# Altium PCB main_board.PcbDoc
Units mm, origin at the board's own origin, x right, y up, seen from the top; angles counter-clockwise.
Board outline 32.69 x 33.15 mm, 2 copper layers (Top Layer, Bottom Layer); 5 components, 23 nets, 61 pads, 28 vias.
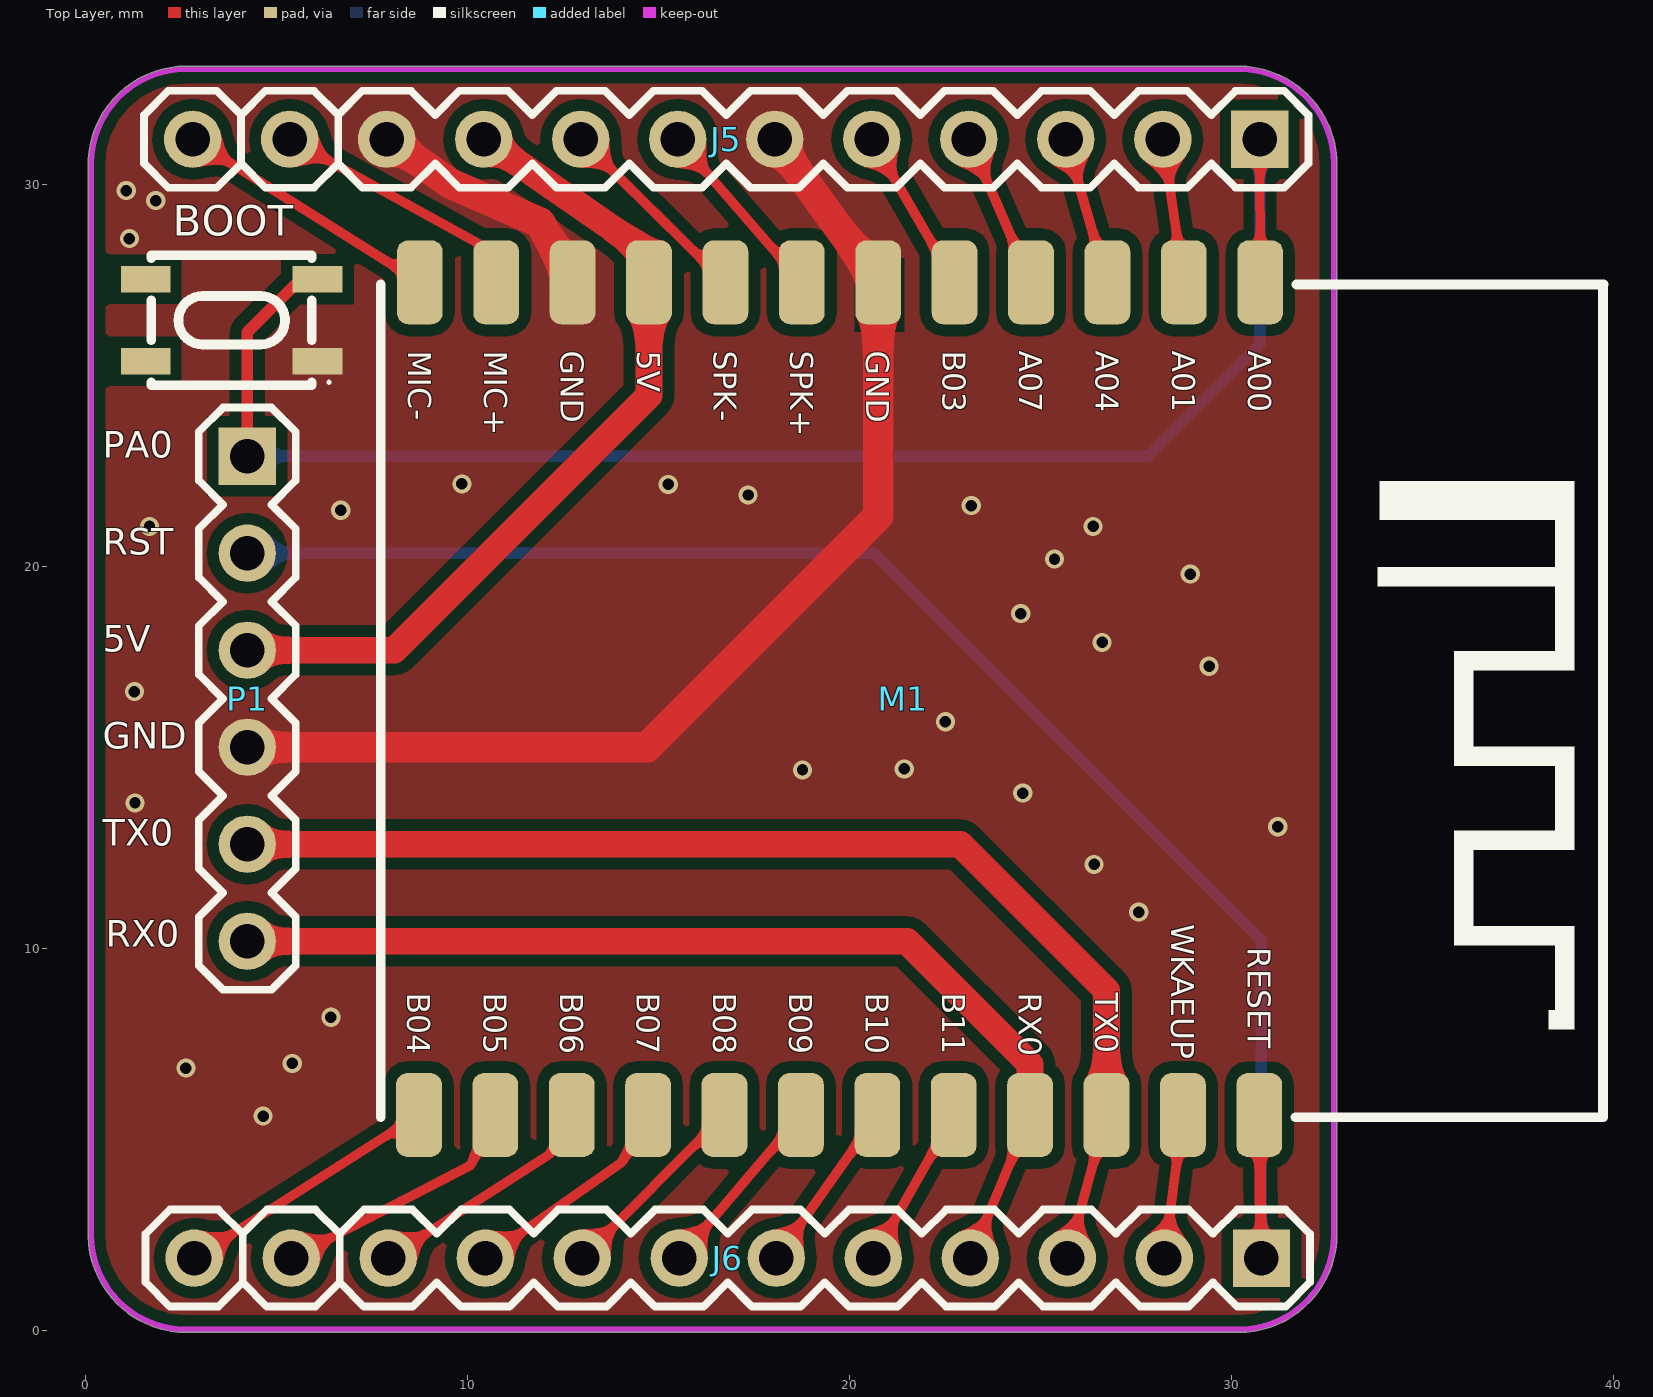
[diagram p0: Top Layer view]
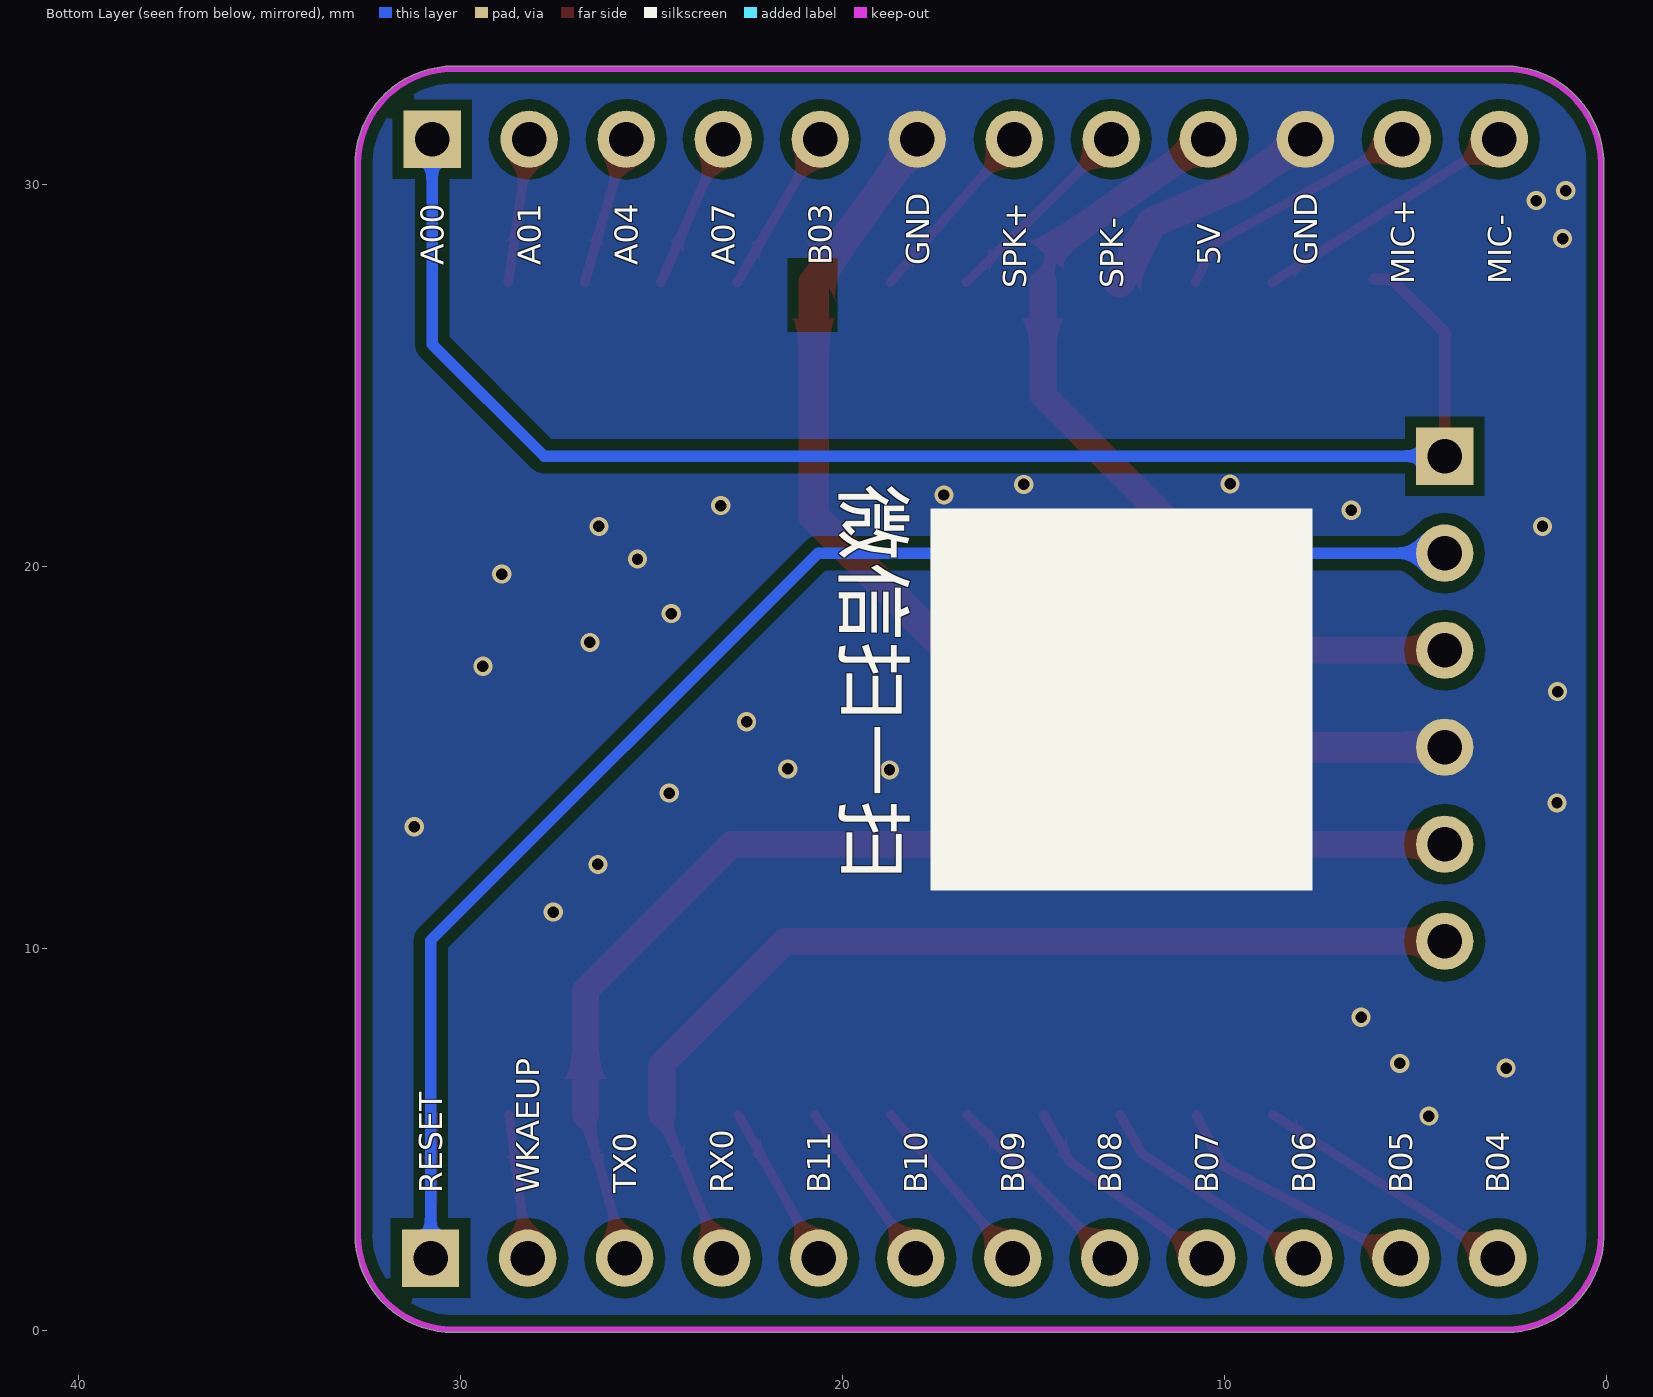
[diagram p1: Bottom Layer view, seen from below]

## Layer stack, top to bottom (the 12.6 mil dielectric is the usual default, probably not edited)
Top Solder: solder mask 0.0102, Solder Resist, Dk 3.5
Top Layer: signal copper 0.0356
Dielectric 1: dielectric 0.32, FR-4, Dk 4.8
Bottom Layer: signal copper 0.0356
Bottom Solder: solder mask 0.0102, Solder Resist, Dk 3.5

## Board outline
0.063,2.486 0.063,30.652 cw(c0.139,30.652) 0.067,30.676 cw(c2.639,30.532) 2.639,33.107 30.179,33.107 cw(c30.179,33.032) 30.179,33.107 cw(c30.179,30.532) 32.748,30.707 cw(c32.679,30.678) 32.754,30.678 32.754,2.532 cw(c30.179,2.532) 30.179,-0.044 2.639,-0.044 cw(c2.639,2.532) 0.064,2.477 cw(c0.139,2.486)

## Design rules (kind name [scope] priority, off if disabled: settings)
Clearance Clearance_freep_ad [HasPad('Free-6') Or HasPad('Free-7') Or HasPad('Free-8') or HasPad('Free-HOLE')] p1: gap=1
Clearance polygon [inpolygon] p2: gap=0.3
Clearance ic [HasFootprint('LQFP48_N') Or HasFootprint('HMC5883L')or HasFootprint('RP4')or HasFootprint('USBMICRO2') Or HasFootprint('JP2_SMD')] p3: gap=0.102
Clearance [All] p4: gap=0.15
ComponentClearance [All] p1: gap=0 collisioncheckmode=3 verticalgap=0.254 showdistances=FALSE
DiffPairsRouting [All] p1: maxlimit=0.254 minlimit=0.2 mostfreqgap=0.2 toplayer_minwidth=0.381 toplayer_maxwidth=0.381 toplayer_prefwidth=0.381 bottomlayer_minwidth=0.381 bottomlayer_maxwidth=0.381 bottomlayer_prefwidth=0.381 maxuncoupledlength=12.7
FabricationTestpoint [(IsPad And (OnTopLayer Or OnBottomLayer))] p1: side=3 testpointundercomponent=TRUE minsize=1.016 maxsize=2.54 preferedsize=1.524 minholesize=0 maxholesize=1.016 preferedholesize=0.813 testpointgrid=0.025 allowsidetop=TRUE allowsidebottom=TRUE usegrid=TRUE gridtolerance=0
HoleSize [All] p1: absolutevalues=TRUE maxlimit=5.08 minlimit=0.152 maxpercent=80.000 minpercent=20.000
MinimumSolderMaskSliver [All] p1: minsoldermaskwidth=0.025
PolygonConnect PolygonConnect_1 [isvia] p1: connectstyle=Direct reliefconductorwidth=0.254 reliefentries=4 polygonreliefangle="90 Angle" airgapwidth=0.254
PolygonConnect [All] p2: connectstyle=Direct reliefconductorwidth=0.254 reliefentries=4 polygonreliefangle="90 Angle" airgapwidth=0.254
RoutingVias [All] p1: holewidth=0.35 width=0.7 viastyle="Through Hole" minholewidth=0.3 minwidth=0.35 maxholewidth=10 maxwidth=10
ShortCircuit ShortCircuit_1 [OnLayer('Mechanical 13')] p1: allowed=TRUE
ShortCircuit [InNet('ANT1') vs InNet('GND')] p2: allowed=TRUE
SilkToSilkClearance [All] p1: silktosilkclearance=0
SilkToSolderMaskClearance SilkscreenOverComponentPads [IsPad] p1: minsilkscreentomaskgap=0.051 clearancetoexposedcopper=TRUE
SolderMaskExpansion [All] p1: expansion=0.051
Width Width_1 [InNet('VCC')] p1: maxlimit=25.4 minlimit=0.178 preferedwidth=0.635
Width [All] p2: maxlimit=10 minlimit=0.2 preferedwidth=0.254
22 further rules are at their usual default settings.

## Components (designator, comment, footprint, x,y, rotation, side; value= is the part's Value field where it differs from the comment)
BOOT "Button" SW-SMD_4P-L4.2-W3.3-P2.15-LS5.1 3.819,26.456 r180 top
J5 "TXD043" PH_12PIN_DIP_2.54MM_180DEG 30.738,31.193 r180 top
J6 "TXD043" PH_12PIN_DIP_2.54MM_180DEG 30.778,1.903 r180 top
M1 "AI-02" WM-AI-Module 21.398,16.548 r270 top locked
P1 "Header_6" PH_6PIN_DIP_2.54MM_180DEG 4.23,22.898 r270 top

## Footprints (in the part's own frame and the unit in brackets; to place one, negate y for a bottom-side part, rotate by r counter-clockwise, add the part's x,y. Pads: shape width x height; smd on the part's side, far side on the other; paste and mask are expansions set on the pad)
PH_6PIN_DIP_2.54MM_180DEG [mm]
  rect 1.5x1.5 hole 0.9: 1(0,0)
  round 1.5 hole 0.9: 2(2.54,0) 3(5.08,0) 4(7.62,0) 5(10.16,0) 6(12.7,0)
  silkscreen extent -1.27,-1.27 13.97,1.27, body extent -1.27,-1.27 13.97,1.27, height 2.62
PH_12PIN_DIP_2.54MM_180DEG [mm]
  rect 1.5x1.5 hole 0.9: 1(0,0)
  round 1.5 hole 0.9: 2(2.54,0) 3(5.08,0) 4(7.62,0) 5(10.16,0) 6(12.7,0) 7(15.24,0) 8(17.78,0) 9(20.32,0) 10(22.86,0) 11(25.4,0) 12(27.94,0)
  silkscreen extent -1.27,-1.27 29.21,1.27
SW-SMD_4P-L4.2-W3.3-P2.15-LS5.1 [mm]
  rect 1.3x0.701 smd mask+0.051: 1(-2.25,1.074) 2(2.25,1.074) 3(-2.25,-1.074) 4(2.25,-1.074)
  silkscreen extent -2.61,-1.7 2.1,1.7
WM-AI-Module [mm]
  rrect50% 2.2x1.2 smd: 1(-10.9,9.348) 2(-10.9,7.348) 3(-10.9,5.348) 4(-10.9,3.348) 5(-10.9,1.348) 6(-10.9,-0.652) 7(-10.9,-2.652) 8(-10.9,-4.652) 9(-10.9,-6.652) 10(-10.9,-8.652) 11(-10.9,-10.652) 12(-10.9,-12.652) 13(10.9,-12.675) 14(10.9,-10.675) 15(10.9,-8.675) 16(10.9,-6.675) 17(10.9,-4.675) 18(10.9,-2.675) 18(10.9,-2.675) 19(10.9,-0.675) 20(10.9,1.325) 21(10.9,3.325) 22(10.9,5.325) 23(10.9,7.325) 24(10.9,9.325)
  rect 0.5x0.5 on Top Overlay: 1(-3.191,12.675)
  rect 1x0.5 on Top Overlay: 2(-5.191,12.675)
  Top Layer pour cut-out: -9.601,0.024 -9.601,-1.262 -11.53,-1.262 -11.53,0.024
  Bottom Layer pour cut-out: -9.601,0.024 -9.601,-1.262 -11.53,-1.262 -11.53,0.024
  silkscreen extent -10.85,-13.68 10.96,18.34

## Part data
J5 J6: "4.3寸TFT 深圳市给力光电有限公司043202B0-40-N"
P1: library part 180DIP_PH_6

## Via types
v1: diameter 0.5, hole 0.3, Top Layer to Bottom Layer, tented both sides, 28 vias

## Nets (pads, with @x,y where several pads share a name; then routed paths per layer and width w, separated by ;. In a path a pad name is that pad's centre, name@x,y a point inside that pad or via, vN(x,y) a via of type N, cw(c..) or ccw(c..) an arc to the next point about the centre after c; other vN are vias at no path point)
5V: J5.9 M1.9 P1.3 | length 22.1
  Top Layer w0.254: M1.9@14.407,28.42 M1.9
  Top Layer w0.7: P1.3 8.08,17.818 14.746,24.484 M1.9 ; J5.9 M1.9@14.407,28.42
A1: J5.2 M1.2@28.746,27.448 | length 3.8
  Top Layer w0.254: J5.2 M1.2@28.746,27.448
A4: J5.3 M1.3 | length 3.9
  Top Layer w0.254: J5.3 M1.3
A7: J5.4 M1.4 | length 4.1
  Top Layer w0.254: J5.4 M1.4
B3: J5.5 M1.5 | length 4.3
  Top Layer w0.254: J5.5 M1.5
B4: J6.12 M1.13 | length 7
  Top Layer w0.254: J6.12 M1.13
B5: J6.11 M1.14 | length 6.8
  Top Layer w0.254: J6.11 10.065,4.327 M1.14
B6: J6.10 M1.15 | length 6.2
  Top Layer w0.254: J6.10 12.135,4.618 M1.15
B7: J6.9 M1.16 | length 5.8
  Top Layer w0.254: J6.9 14.023,4.4 M1.16
B8: J6.8 M1.17 | length 5.3
  Top Layer w0.254: J6.8 M1.17
B9: J6.7 M1.18 | length 4.9
  Top Layer w0.254: J6.7 M1.18@18.723,5.648
B10: J6.6 M1.19 | length 4.6
  Top Layer w0.254: J6.6 M1.19
B11: J6.5 M1.20 | length 4.3
  Top Layer w0.254: J6.5 M1.20
BOOT: BOOT.3 J5.1 M1.1@30.746,27.448 P1.1 | length 42.5
  Top Layer w0.254: J5.1 M1.1@30.746,27.448
  Top Layer w0.3: P1.1 4.23,26.14 5.62,27.53 BOOT.3
  Bottom Layer w0.3: P1.1 27.808,22.898 30.738,25.828 J5.1
GND: BOOT.1 J5.6 J5.10 M1.6 M1.10 P1.4 | length 36.1
  Top Layer w0.8: P1.4 14.693,15.278 20.746,21.331 M1.6 J5.6 ; J5.10 9.555,30.028 11.894,29.008 M1.10
  other v1: 4.645,5.619 2.624,6.877 5.407,7.001 6.417,8.208 27.566,10.961 26.399,12.209 31.207,13.196 1.29,13.822 24.531,14.077 18.764,14.685 21.427,14.709 22.507,15.945 1.274,16.732 29.409,17.398 26.606,18.021 24.477,18.776 28.916,19.811 25.361,20.2 1.67,21.057 26.373,21.057 6.677,21.48 23.181,21.602 17.342,21.88 15.251,22.159 9.846,22.173 1.142,28.592 1.834,29.589 1.061,29.847
MIC+: J5.11 M1.11 | length 6.8
  Top Layer w0.254: J5.11 10.244,28.484 M1.11
MIC-: J5.12 M1.12 | length 7
  Top Layer w0.254: J5.12 M1.12
RESET: J6.1 M1.24 P1.2 | length 42.8
  Top Layer w0.3: M1.24 J6.1
  Bottom Layer w0.3: P1.2 20.636,20.358 30.778,10.216 J6.1
SPK+: J5.7 M1.7 | length 5
  Top Layer w0.254: J5.7 M1.7
SPK-: J5.8 M1.8 | length 5.3
  Top Layer w0.254: J5.8 M1.8
UART0_RX: J6.4 M1.21 P1.6 | length 27.2
  Top Layer w0.254: J6.4 M1.21
  Top Layer w0.7: P1.6 21.505,10.198 24.723,6.98 M1.21
UART0_TX: J6.3 M1.22 P1.5 | length 31.2
  Top Layer w0.254: J6.3 M1.22
  Top Layer w0.7: P1.5 22.891,12.738 26.723,8.906 M1.22
WAKEUP: J6.2 M1.23 | length 3.8
  Top Layer w0.254: J6.2 M1.23
pads on no net: BOOT.2 BOOT.4 M1.1@34.073,19.739 M1.2@34.073,21.739

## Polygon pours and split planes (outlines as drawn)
GND on Bottom Layer "Top Layer-No Net" (solid, remove dead copper, pour order 16): -18.537,40.067 67.397,40.067 67.04,40.067 67.04,-4.944 67.04,-4.484 -16.8,-4.484 -18.537,-4.484
GND on Top Layer "Top Layer-No Net" (solid, remove dead copper, pour order 14): -24.986,39.589 60.948,39.589 60.591,39.589 60.591,-5.422 60.591,-4.962 -23.249,-4.962 -24.986,-4.962

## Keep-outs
Keep-Out Layer:
  lines w0.15: 0.139,2.486 0.139,30.652 ; 0.139,2.532 ccw(c2.639,2.532) 2.639,0.032 30.179,0.032 ccw(c30.179,2.532) 32.679,2.532 32.679,30.678 ; 0.139,30.532 cw(c2.639,30.532) 2.639,33.032 30.179,33.032 cw(c30.179,30.532) 32.679,30.532

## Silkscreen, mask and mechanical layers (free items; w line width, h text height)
Top Overlay:
  text "PA0" at 0.444,22.617 h1.2
  text "RST" at 0.444,20.077 h1.2
  text "5V" at 0.444,17.537 h1.2
  text "GND" at 0.444,14.997 h1.2
  text "TX0" at 0.444,12.457 h1.2
  text "RX0" at 0.53,9.821 h1.2
Bottom Overlay:
  rectangle: 7.692,11.529 17.692,21.529
  text "GND" at 7.57,27.896 h0.6 r270
  text "5V" at 10.11,27.896 h0.6 r270
  text "GND" at 17.73,27.896 h0.6 r270
  text "B03" at 20.27,27.896 h0.6 r270
  text "A07" at 22.81,27.896 h0.6 r270
  text "A04" at 25.35,27.896 h0.6 r270
  text "A01" at 27.89,27.896 h0.6 r270
  text "A00" at 30.43,27.896 h0.6 r270
  text "MIC-" at 2.49,27.396 h0.6 r270
  text "MIC+" at 5.03,27.396 h0.6 r270
  text "SPK-" at 12.65,27.296 h0.6 r270
  text "SPK+" at 15.19,27.296 h0.6 r270
  text "微信扫一扫" at 20.408,22.215 h2.6 r90
  text "B04" at 2.538,3.6 h0.6 r270
  text "B05" at 5.078,3.6 h0.6 r270
  text "B06" at 7.618,3.6 h0.6 r270
  text "B07" at 10.158,3.6 h0.6 r270
  text "B08" at 12.698,3.6 h0.6 r270
  text "B09" at 15.238,3.6 h0.6 r270
  text "B10" at 17.778,3.6 h0.6 r270
  text "B11" at 20.318,3.6 h0.6 r270
  text "RX0" at 22.858,3.6 h0.6 r270
  text "TX0" at 25.398,3.6 h0.6 r270
  text "WKAEUP" at 27.938,3.6 h0.6 r270
  text "RESET" at 30.478,3.6 h0.6 r270

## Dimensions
2.639,0.032 to 2.639,33.032 on Mechanical 15
0.139,30.652 to 32.679,30.678 on Mechanical 15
